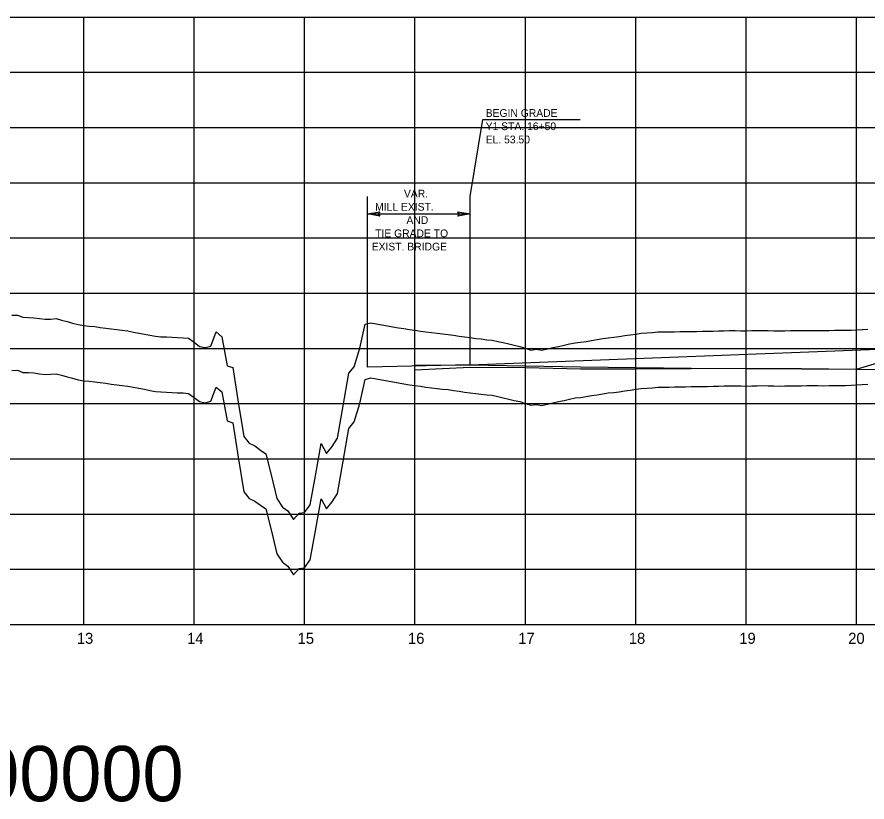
# Model space of a CAD drawing. Extents: x 2345490 to 2436403, y 465165 to 573888.
# Drawn here: x 2381561 to 2382331, y 557623 to 558334 of the extents above; entities that cross this region are included whole.
import ezdxf

# ---------------------------------------------------------------- set-up
doc = ezdxf.new("R2010")
doc.units = 0
for name, color, linetype in [('Old_Level_1', 7, 'Continuous'), ('Old_Level_11', 7, 'Continuous'), ('Old_Level_2', 7, 'Continuous'), ('Old_Level_3', 7, 'Continuous'), ('Old_Level_57', 7, 'Continuous'), ('Old_Level_62', 7, 'Continuous'), ('Old_Level_63', 7, 'Continuous')]:
    doc.layers.add(name, color=color, linetype=linetype)

msp = doc.modelspace()

# ---------------------------------------------------------------- linework, layer by layer
at = {"layer": 'Old_Level_1'}
for points in [[(2381556.5425, 558014.17975), (2381561.5425, 558014.345), (2381566.5425, 558012.34825), (2381571.5425, 558012.16725), (2381576.5425, 558011.94), (2381581.5425, 558011.17425), (2381586.5425, 558010.51125), (2381591.5425, 558010.687), (2381596.5425, 558011.06275), (2381601.5425, 558009.82075), (2381606.5425, 558008.45275), (2381611.5425, 558007.08475), (2381616.5425, 558005.71675), (2381621.5425, 558004.79225), (2381626.5425, 558004.3155), (2381631.5425, 558003.8705), (2381636.5425, 558003.1865), (2381641.5425, 558002.5025), (2381646.5425, 558001.8185), (2381651.5425, 558001.13425), (2381656.5425, 558000.66125), (2381661.5425, 557999.9125), (2381666.5425, 557998.971), (2381671.5425, 557998.0295), (2381676.5425, 557997.08775), (2381681.5425, 557996.14625), (2381686.5425, 557995.2045), (2381691.5425, 557994.73), (2381696.5425, 557994.4985), (2381701.5425, 557994.267), (2381706.5425, 557994.0355), (2381711.5425, 557993.804), (2381716.5425, 557993.32975), (2381721.5425, 557989.6355), (2381726.5425, 557985.94125), (2381731.5425, 557984.98625), (2381736.5425, 557986.2335), (2381741.5425, 557999.0015), (2381746.5425, 557994.703), (2381751.5425, 557968.47525), (2381756.5425, 557966.72025), (2381761.5425, 557935.573), (2381766.5425, 557904.265), (2381771.5425, 557898.2835), (2381776.5425, 557895.816), (2381781.5425, 557892.12), (2381786.5425, 557888.74425), (2381791.5425, 557868.562), (2381796.5425, 557848.07025), (2381801.5425, 557840.46725), (2381806.5425, 557836.9425), (2381811.5425, 557829.2295), (2381816.5425, 557834.94425), (2381821.5425, 557835.4735)], [(2381821.5425, 557835.4735), (2381826.5425, 557842.55175), (2381831.5425, 557868.86125), (2381836.5425, 557897.972), (2381841.5425, 557888.876), (2381846.5425, 557895.1565), (2381851.5425, 557902.77325), (2381856.5425, 557932.17375), (2381861.5425, 557961.7105), (2381866.5425, 557967.49875), (2381871.5425, 557984.313), (2381876.5425, 558006.1115), (2381881.5425, 558007.383), (2381886.5425, 558006.46575), (2381891.5425, 558005.54825), (2381896.5425, 558004.631), (2381901.5425, 558003.71375), (2381906.5425, 558002.83775), (2381911.5425, 558002.06725), (2381916.5425, 558001.172), (2381921.5425, 558000.54175), (2381926.5425, 557999.8575), (2381931.5425, 557999.1735), (2381936.5425, 557998.48925), (2381941.5425, 557997.805), (2381946.5425, 557997.179), (2381951.5425, 557996.79725), (2381956.5425, 557996.081), (2381961.5425, 557995.3495), (2381966.5425, 557994.61775), (2381971.5425, 557993.886), (2381976.5425, 557993.1545), (2381981.5425, 557992.68725), (2381986.5425, 557992.0265), (2381991.5425, 557991.646), (2381996.5425, 557990.494), (2382001.5425, 557989.34175), (2382006.5425, 557988.18975), (2382011.5425, 557987.0375), (2382016.5425, 557985.99625), (2382021.5425, 557984.32225), (2382026.5425, 557982.6485), (2382031.5425, 557983.37), (2382036.5425, 557982.47925), (2382041.5425, 557983.745), (2382046.5425, 557984.8645), (2382051.5425, 557985.98375), (2382056.5425, 557987.103), (2382061.5425, 557988.22225), (2382066.5425, 557989.268), (2382071.5425, 557989.69), (2382076.5425, 557990.5245), (2382081.5425, 557991.359), (2382086.5425, 557992.19325), (2382091.5425, 557993.02775), (2382096.5425, 557993.7575), (2382101.5425, 557994.17975), (2382106.5425, 557994.94725), (2382111.5425, 557995.6835), (2382116.5425, 557996.4195), (2382121.5425, 557997.15575), (2382126.5425, 557997.89175), (2382131.5425, 557998.0865), (2382136.5425, 557998.51875), (2382141.5425, 557999.01325), (2382146.5425, 557999.0895), (2382151.5425, 557999.16075), (2382156.5425, 557999.23225), (2382161.5425, 557999.30375), (2382166.5425, 557999.38925), (2382171.5425, 557999.4855), (2382176.5425, 557999.565), (2382181.5425, 557999.64425), (2382186.5425, 557999.7415), (2382191.5425, 557999.83875), (2382196.5425, 557999.9775), (2382201.5425, 558000.11825), (2382206.5425, 558000.25875), (2382211.5425, 558000.34), (2382216.5425, 558000.1565), (2382221.5425, 558000.06275), (2382226.5425, 558000.18825), (2382231.5425, 558000.314), (2382236.5425, 558000.4395), (2382241.5425, 558000.35), (2382246.5425, 558000.15375), (2382251.5425, 558000.0405), (2382256.5425, 558000.16975), (2382261.5425, 558000.278), (2382266.5425, 558000.263), (2382271.5425, 558000.3275), (2382276.5425, 558000.392), (2382281.5425, 558000.4565), (2382286.5425, 558000.454), (2382291.5425, 558000.388), (2382296.5425, 558000.41875), (2382301.5425, 558000.49725), (2382306.5425, 558000.55625), (2382311.5425, 558000.50225), (2382316.5425, 558000.74825), (2382321.5425, 558001.0325)], [(2382321.5425, 558001.0325), (2382326.5425, 558001.31675), (2382331.5425, 558001.601)]]:
    msp.add_lwpolyline(points, dxfattribs=at)
at = {"layer": 'Old_Level_11'}
for points in [[(2381889.7165, 558153.94875), (2381878.4665, 558155.88625), (2381889.779, 558157.88625), (2381888.3415, 558155.88625)], [(2381960.2925, 558157.82375), (2381971.5425, 558155.88625), (2381960.23, 558153.88625), (2381961.6675, 558155.88625)]]:
    msp.add_lwpolyline(points, close=True, dxfattribs=at)
at = {"layer": 'Old_Level_2'}
for q in [(2382671.5425, 558046.335), (2381878.4665, 558016.9915)]:
    msp.add_line((2381971.5425, 558019.113), q, dxfattribs=at)
at = {"layer": 'Old_Level_3'}
for p, q in [((2381971.5425, 558171.59525), (2381982.94325, 558241.3935)), ((2381982.94325, 558241.3935), (2382071.25325, 558241.3935)), ((2381878.4665, 558016.9915), (2381878.4665, 558171.59525)), ((2381971.5425, 558019.113), (2381971.5425, 558171.59525)), ((2381878.4665, 558155.88625), (2381971.5425, 558155.88625))]:
    msp.add_line(p, q, dxfattribs=at)
at = {"layer": 'Old_Level_57'}
for p, q in [((2381271.54275, 558334.11325), (2393041.55275, 558334.11325)), ((2381621.54225, 557784.21325), (2381621.54225, 558334.21325)), ((2381621.54225, 557784.11325), (2381621.54225, 558334.11325)), ((2381721.54225, 557784.21325), (2381721.54225, 558334.21325)), ((2381721.54225, 557784.11325), (2381721.54225, 558334.11325)), ((2381821.54225, 557784.21325), (2381821.54225, 558334.21325)), ((2381821.54225, 557784.11325), (2381821.54225, 558334.11325)), ((2381921.54225, 557784.21325), (2381921.54225, 558334.21325)), ((2381921.54225, 557784.11325), (2381921.54225, 558334.11325)), ((2382021.54225, 557784.21325), (2382021.54225, 558334.21325)), ((2382021.54225, 557784.11325), (2382021.54225, 558334.11325)), ((2382121.54225, 557784.21325), (2382121.54225, 558334.21325)), ((2382121.54225, 557784.11325), (2382121.54225, 558334.11325)), ((2382221.54225, 557784.21325), (2382221.54225, 558334.21325)), ((2382221.54225, 557784.11325), (2382221.54225, 558334.11325)), ((2382321.54225, 557784.21325), (2382321.54225, 558334.21325)), ((2382321.54225, 557784.11325), (2382321.54225, 558334.11325)), ((2381271.54275, 558284.11325), (2393041.55275, 558284.11325)), ((2381271.54275, 558234.11325), (2393041.55275, 558234.11325)), ((2381271.54275, 558184.11325), (2393041.55275, 558184.11325)), ((2381271.54275, 558134.11325), (2393041.55275, 558134.11325)), ((2381271.54275, 558084.11325), (2393041.55275, 558084.11325)), ((2381271.5425, 558034.11325), (2393041.55275, 558034.11325)), ((2381271.54275, 557984.11325), (2393041.55275, 557984.11325)), ((2381271.5425, 557934.11325), (2393041.55275, 557934.11325)), ((2381271.54275, 557884.11325), (2393041.55275, 557884.11325)), ((2381271.5425, 557834.11325), (2393041.55275, 557834.11325)), ((2381271.54275, 557784.11325), (2393041.55275, 557784.11325))]:
    msp.add_line(p, q, dxfattribs=at)
at = {"layer": 'Old_Level_62'}
for points in [[(2381556.5425, 558064.18575), (2381561.5425, 558064.351), (2381566.5425, 558062.35425), (2381571.5425, 558062.17325), (2381576.5425, 558061.946), (2381581.5425, 558061.18025), (2381586.5425, 558060.51725), (2381591.5425, 558060.693), (2381596.5425, 558061.06875), (2381601.5425, 558059.82675), (2381606.5425, 558058.45875), (2381611.5425, 558057.09075), (2381616.5425, 558055.72275), (2381621.5425, 558054.79825), (2381626.5425, 558054.3215), (2381631.5425, 558053.8765), (2381636.5425, 558053.1925), (2381641.5425, 558052.5085), (2381646.5425, 558051.8245), (2381651.5425, 558051.14025), (2381656.5425, 558050.66725), (2381661.5425, 558049.9185), (2381666.5425, 558048.977), (2381671.5425, 558048.0355), (2381676.5425, 558047.09375), (2381681.5425, 558046.15225), (2381686.5425, 558045.2105), (2381691.5425, 558044.736), (2381696.5425, 558044.5045), (2381701.5425, 558044.273), (2381706.5425, 558044.0415), (2381711.5425, 558043.81), (2381716.5425, 558043.33575), (2381721.5425, 558039.6415), (2381726.5425, 558035.94725), (2381731.5425, 558034.99225), (2381736.5425, 558036.2395), (2381741.5425, 558049.0075), (2381746.5425, 558044.709), (2381751.5425, 558018.48125), (2381756.5425, 558016.72625), (2381761.5425, 557985.579), (2381766.5425, 557954.271), (2381771.5425, 557948.2895), (2381776.5425, 557945.822), (2381781.5425, 557942.126), (2381786.5425, 557938.75025), (2381791.5425, 557918.568), (2381796.5425, 557898.07625), (2381801.5425, 557890.47325), (2381806.5425, 557886.9485), (2381811.5425, 557879.2355), (2381816.5425, 557884.95025), (2381821.5425, 557885.4795)], [(2381821.5425, 557885.4795), (2381826.5425, 557892.55775), (2381831.5425, 557918.86725), (2381836.5425, 557947.978), (2381841.5425, 557938.882), (2381846.5425, 557945.1625), (2381851.5425, 557952.77925), (2381856.5425, 557982.17975), (2381861.5425, 558011.7165), (2381866.5425, 558017.50475), (2381871.5425, 558034.319), (2381876.5425, 558056.1175), (2381881.5425, 558057.389), (2381886.5425, 558056.47175), (2381891.5425, 558055.55425), (2381896.5425, 558054.637), (2381901.5425, 558053.71975), (2381906.5425, 558052.84375), (2381911.5425, 558052.07325), (2381916.5425, 558051.178), (2381921.5425, 558050.54775), (2381926.5425, 558049.8635), (2381931.5425, 558049.1795), (2381936.5425, 558048.49525), (2381941.5425, 558047.811), (2381946.5425, 558047.185), (2381951.5425, 558046.80325), (2381956.5425, 558046.087), (2381961.5425, 558045.3555), (2381966.5425, 558044.62375), (2381971.5425, 558043.892), (2381976.5425, 558043.1605), (2381981.5425, 558042.69325), (2381986.5425, 558042.0325), (2381991.5425, 558041.652), (2381996.5425, 558040.5), (2382001.5425, 558039.34775), (2382006.5425, 558038.19575), (2382011.5425, 558037.0435), (2382016.5425, 558036.00225), (2382021.5425, 558034.32825), (2382026.5425, 558032.6545), (2382031.5425, 558033.376), (2382036.5425, 558032.48525), (2382041.5425, 558033.751), (2382046.5425, 558034.8705), (2382051.5425, 558035.98975), (2382056.5425, 558037.109), (2382061.5425, 558038.22825), (2382066.5425, 558039.274), (2382071.5425, 558039.696), (2382076.5425, 558040.5305), (2382081.5425, 558041.365), (2382086.5425, 558042.19925), (2382091.5425, 558043.03375), (2382096.5425, 558043.7635), (2382101.5425, 558044.18575), (2382106.5425, 558044.95325), (2382111.5425, 558045.6895), (2382116.5425, 558046.4255), (2382121.5425, 558047.16175), (2382126.5425, 558047.89775), (2382131.5425, 558048.0925), (2382136.5425, 558048.52475), (2382141.5425, 558049.01925), (2382146.5425, 558049.0955), (2382151.5425, 558049.16675), (2382156.5425, 558049.23825), (2382161.5425, 558049.30975), (2382166.5425, 558049.39525), (2382171.5425, 558049.4915), (2382176.5425, 558049.571), (2382181.5425, 558049.65025), (2382186.5425, 558049.7475), (2382191.5425, 558049.84475), (2382196.5425, 558049.9835), (2382201.5425, 558050.12425), (2382206.5425, 558050.26475), (2382211.5425, 558050.346), (2382216.5425, 558050.1625), (2382221.5425, 558050.06875), (2382226.5425, 558050.19425), (2382231.5425, 558050.32), (2382236.5425, 558050.4455), (2382241.5425, 558050.356), (2382246.5425, 558050.15975), (2382251.5425, 558050.0465), (2382256.5425, 558050.17575), (2382261.5425, 558050.284), (2382266.5425, 558050.269), (2382271.5425, 558050.3335), (2382276.5425, 558050.398), (2382281.5425, 558050.4625), (2382286.5425, 558050.46), (2382291.5425, 558050.394), (2382296.5425, 558050.42475), (2382301.5425, 558050.50325), (2382306.5425, 558050.56225), (2382311.5425, 558050.50825), (2382316.5425, 558050.75425), (2382321.5425, 558051.0385)], [(2382321.5425, 558051.0385), (2382326.5425, 558051.32275), (2382331.5425, 558051.607)], [(2381921.5425, 558014.613), (2381971.5425, 558017.013), (2382021.5425, 558016.713), (2382071.5425, 558015.713), (2382121.5425, 558015.613), (2382171.5425, 558016.013), (2382221.5425, 558016.113), (2382271.5425, 558015.713), (2382321.5425, 558015.213), (2382371.5425, 558030.313), (2382421.5425, 558029.713), (2382471.5425, 558028.413), (2382521.5425, 558027.213), (2382571.5425, 558026.613), (2382621.5425, 558023.713), (2382671.5425, 558023.013), (2382721.5425, 558021.313)], [(2381921.5425, 558018.913), (2381971.5425, 558019.113), (2382021.5425, 558018.313), (2382071.5425, 558017.413), (2382121.5425, 558016.713), (2382171.5425, 558016.113), (2382221.5425, 558016.013), (2382271.5425, 558016.013), (2382321.5425, 558015.213), (2382371.5425, 558015.013), (2382421.5425, 558013.913), (2382471.5425, 558012.513), (2382521.5425, 558010.713), (2382571.5425, 558005.613), (2382621.5425, 558024.813), (2382671.5425, 558021.113), (2382721.5425, 558017.413), (2382771.5425, 558011.613), (2382821.5425, 558018.413), (2382871.5425, 558022.913), (2382921.5425, 558014.613), (2382971.5425, 558004.513)]]:
    msp.add_lwpolyline(points, dxfattribs=at)
at = {"layer": 'Old_Level_63'}
msp.add_line((2381321.5425, 557784.113), (2393019.104, 557784.113), dxfattribs=at)

# ---------------------------------------------------------------- texts
at = {"layer": 'Old_Level_1'}
for s, p in [('13', (2381615.3485, 557766.613)), ('14', (2381715.191, 557766.613)), ('15', (2381815.2835, 557766.613)), ('16', (2381915.2245, 557766.613)), ('17', (2382015.082, 557766.613)), ('18', (2382115.20775, 557766.613)), ('19', (2382215.25, 557766.613)), ('20', (2382313.929, 557766.613))]:
    msp.add_text(s, height=10.000001, dxfattribs=at).set_placement(p)
at = {"layer": 'Old_Level_3'}
for s, height, p in [('BEGIN GRADE', 7.0000005, (2381985.63675, 558243.78925)), ('Y1 STA. 16+50', 7.0000005, (2381985.63675, 558231.789)), ('EL. 53.50', 7.000001, (2381985.63675, 558219.789)), ('VAR.', 7.000001, (2381911.578, 558170.8265)), ('MILL EXIST. ', 7.0000005, (2381885.481, 558158.8265)), ('AND', 7.000001, (2381913.865, 558146.8265)), ('TIE GRADE TO', 7.0000005, (2381885.5145, 558134.82625)), ('EXIST. BRIDGE', 7.0000005, (2381882.368, 558122.82625))]:
    msp.add_text(s, height=height, dxfattribs=at).set_placement(p)
at = {"layer": 'Old_Level_63'}
msp.add_text('1000.000000', height=49.9999995, dxfattribs=at).set_placement((2381321.5425, 557624.113))

doc.saveas('drawing.dxf')
